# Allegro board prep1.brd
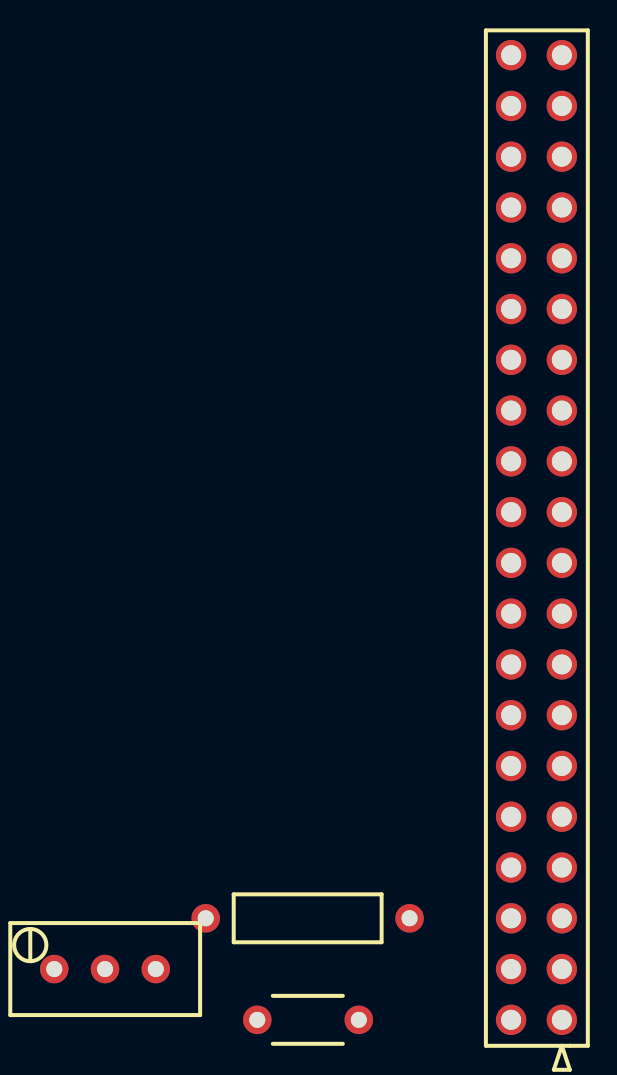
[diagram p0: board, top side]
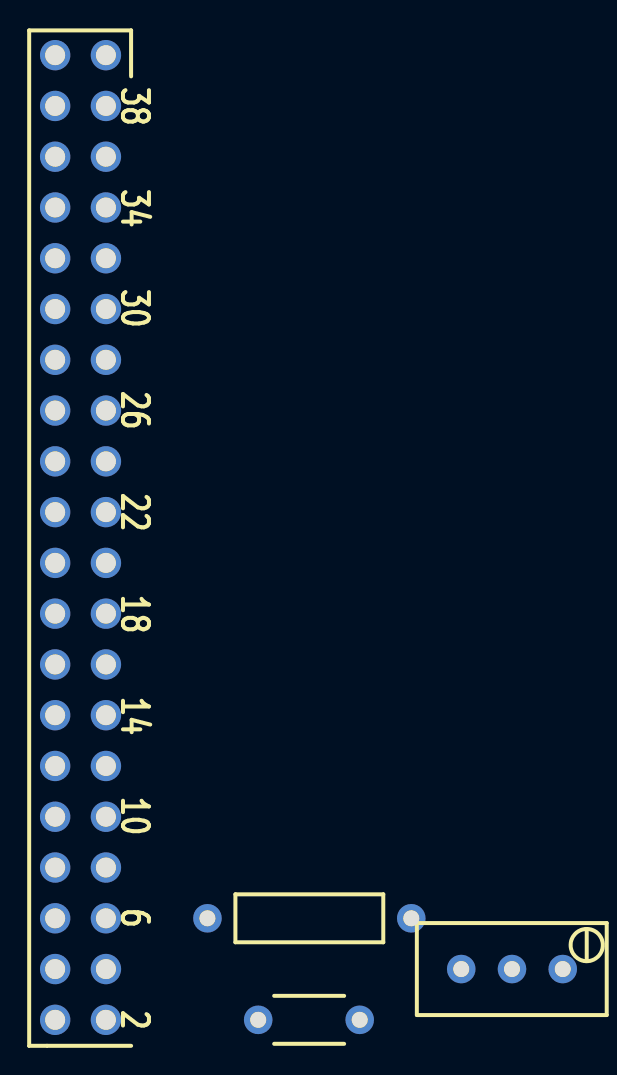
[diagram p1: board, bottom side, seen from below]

No outline. copper layers: TOP, BOTTOM. Coordinates in mm from the lowest, leftmost part position.

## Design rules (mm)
constraint set DEFAULT: min track width 0.15, pair gap 0.15

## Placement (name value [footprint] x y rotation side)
J1  -  [CONHE13D2X20M]  25.4 0 0 top
PO1  100  [POT45X95D]  0 2.54 0 top
R1  100  [R50]  15.24 0 180 top
R2  100  [R100]  17.78 5.08 180 top

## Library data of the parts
J1 = CON40P: part number: CON40P-HE13D
PO1 = POT: part number: POT-100,1/2W20T_D
R1 = RGEN: part number: RGEN-100,C125MW5%
R2 = RGEN: part number: RGEN-100,M500MW5%

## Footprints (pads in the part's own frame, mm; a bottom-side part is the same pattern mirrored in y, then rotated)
CONHE13D2X20M
  round 1.52 hole 1: 1(0,0) 2(-2.54,0) 3(0,2.54) 4(-2.54,2.54) 5(0,5.08) 6(-2.54,5.08) 7(0,7.62) 8(-2.54,7.62) 9(0,10.16) 10(-2.54,10.16) 11(0,12.7) 12(-2.54,12.7) 13(0,15.24) 14(-2.54,15.24) 15(0,17.78) 16(-2.54,17.78) 17(0,20.32) 18(-2.54,20.32) 19(0,22.86) 20(-2.54,22.86) 21(0,25.4) 22(-2.54,25.4) 23(0,27.94) 24(-2.54,27.94) 25(0,30.48) 26(-2.54,30.48) 27(0,33.02) 28(-2.54,33.02) 29(0,35.56) 30(-2.54,35.56) 31(0,38.1) 32(-2.54,38.1) 33(0,40.64) 34(-2.54,40.64) 35(0,43.18) 36(-2.54,43.18) 37(0,45.72) 38(-2.54,45.72) 39(0,48.26) 40(-2.54,48.26)
POT45X95D
  round 1.43 hole 0.8: 1(0,0) 2(2.54,0) 3(5.08,0)
R50
  round 1.43 hole 0.8: 1(0,0) 2(5.08,0)
R100
  round 1.43 hole 0.8: 1(0,0) 2(10.2,0)

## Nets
GND: J1.1 J1.3 J1.5 J1.7 J1.9 J1.11 J1.13 J1.15 J1.17 J1.19 J1.21 J1.23 J1.25 J1.27 J1.29 J1.31 J1.33 J1.35 J1.37 J1.39
UNNAMED_1_CON40P_I1_A: J1.2 R1.1
UNNAMED_1_CON40P_I1_A_1: J1.4 R2.1
UNNAMED_1_CON40P_I1_A_2: J1.26
UNNAMED_1_CON40P_I1_A_3: J1.24
UNNAMED_1_CON40P_I1_A_4: J1.22
UNNAMED_1_CON40P_I1_A_5: J1.20
UNNAMED_1_CON40P_I1_A_6: J1.18
UNNAMED_1_CON40P_I1_A_7: J1.16
UNNAMED_1_CON40P_I1_A_8: J1.14
UNNAMED_1_CON40P_I1_A_9: J1.12
UNNAMED_1_CON40P_I1_A_10: J1.10(A<9>)
UNNAMED_1_CON40P_I1_A_11: J1.8
UNNAMED_1_CON40P_I1_A_12: J1.6
UNNAMED_1_CON40P_I1_A_13: J1.40
UNNAMED_1_CON40P_I1_A_14: J1.36
UNNAMED_1_CON40P_I1_A_15: J1.34
UNNAMED_1_CON40P_I1_A_16: J1.32
UNNAMED_1_CON40P_I1_A_17: J1.38
UNNAMED_1_CON40P_I1_A_18: J1.30
UNNAMED_1_CON40P_I1_A_19: J1.28
UNNAMED_1_POT_I5_A: PO1.1
UNNAMED_1_POT_I5_B: PO1.2 R1.2(B<0>)
UNNAMED_1_POT_I7_B: R2.2(B<0>)

Pads without a net: PO1 3
